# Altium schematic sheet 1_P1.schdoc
size 307 x 218 mm; Symbol: Drawing-Symbol_A4; Device: Drawing-Symbol_A4; Company: 嘉立创EDA; Version: V1.0; Page Size: A4; @Project Name: 温度检测; @Page Count: 1; @Update Date: 2025-09-01; @Create Date: 2025-09-01; @Schematic Name: Schematic1; @Page No: 1; @Page Name: P1; @Create Time: 12:47:40; @Update Time: 20:47:40; Width: 1170; Height: 825; Region Start: 1; X Region Count: 6; Y Region Count: 4; Blade Width: 10; Title Block Position: 3; @Board Name: Board1
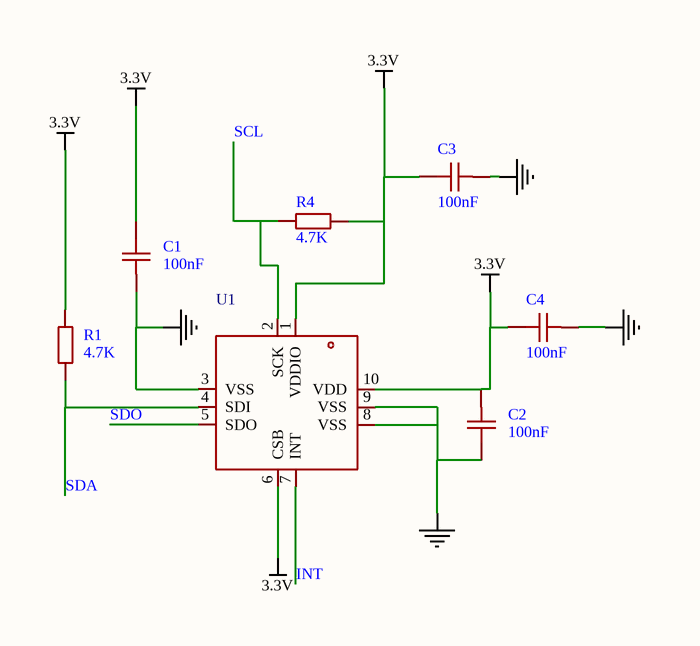
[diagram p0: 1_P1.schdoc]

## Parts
C1  100nF  [C0603]
C2  100nF  [C0603]
C3  100nF  [C0603]
C4  100nF  [C0603]
R1  4.7K  [R0603]
R4  4.7K  [R0603]
U1  BMP388  [SENSORM-SMD_BMP388]  (value not drawn)

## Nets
3.3V: C1.1 C2.2 C3.1 C4.1 R1.1 R4.1 U1.1(VDDIO) U1.6(CSB) U1.10(VDD)
GND: C1.2 C2.1 C3.2 C4.2 U1.3(VSS) U1.8(VSS) U1.9(VSS)
INT: U1.7(INT)
SCL: R4.2 U1.2(SCK)
SDA: R1.2 U1.4(SDI)
SDO: U1.5(SDO)

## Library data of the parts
C1-C4 = CAP_0603: Symbol: Capacitance; Convert to PCB: yes
R1 R4 = Res_0603: Symbol: 电阻; Convert to PCB: yes
U1 = BMP388: Manufacturer: Bosch(博世); Add into BOM: yes; Pressure range: 30Kpa~125Kpa; Voltage - Supply: 1.65V~3.6V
